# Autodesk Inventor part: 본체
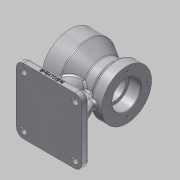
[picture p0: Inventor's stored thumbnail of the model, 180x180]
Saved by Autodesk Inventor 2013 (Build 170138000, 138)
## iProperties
Created: 2019-01
Part Number: 본체
Material: 알루미늄 6061
Document SubType Name: Modeling
Designer: dgall
Density: 2.71 g/cm^3
Mass: 902.149 g
Surface Area: 600.961 cm^2
Volume: 332.896 cm^3
Author: dgall
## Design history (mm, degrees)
sketch "스케치1"
  geometry: L1 (46, 46)-(-46, 46); L2 (-46, 46)-(-46, -46); L3 (-46, -46)-(46, -46); L4 (46, -46)-(46, 46); L5 (46, 46)-(-46, -46); L6 (-46, 46)-(46, -46); 1 further point
  constraints: 12 end point, 2 midpoint, 2 parallel, 1 horizontal, 1 perpendicular
  dimensions: "d0" = 92 distance of L1.end L2.end; "d2" = 92 distance of L2.end L3.end
extrude "돌출1" new body sketch "스케치1" distance "d3" = 10; taper "d4" = 0 deg
sketch "스케치2"
  geometry: L1 (46, -46)-(46, 46) reference; L2 (-46, 46)-(-46, -46) reference; L3 (-46, 0)-(-16, 0); L4 (-16, 0)-(36, 0); L5 (-0.801, -5)-(36, -5); L6 (36, -5)-(36, 5); L7 (36, 5)-(-0.801, 5); L8 (-5.291, -5)-(36, 5); L9 (36, -5)-(-5.291, 5); A1 r 16 centre (-16, 0) between (-0.801, 5) and (-0.801, -5); 2 further points
  constraints: 14 end point, 3 midpoint, 3 perpendicular, 2 parallel, 2 point on circle, 1 centre point, 1 coincident, 1 point on line
  dimensions: "d5" = 30 distance of L3.start L3.end; "d7" = 32 diameter of A1; "d8" = 10 distance from line of L1 L4.end; "d9" = 10 distance of L6.end L5.end
extrude "돌출2" join sketch "스케치2" distance "d10" = 70; taper "d11" = 0 deg
sketch "스케치3"
  geometry: L1 (36.801, 0)-(2.798, 72.92); L2 (46.801, -10)-(46.801, 0) reference; L3 (2.798, 72.92)-(46.801, 72.92); L4 (46.801, 72.92)-(36.801, 0); 1 further point
  constraints: 6 end point, 1 perpendicular
  dimensions: "d12" = 25 deg angle of L2 L1
extrude "돌출3" cut sketch "스케치3" distance "d13" = 70; taper "d14" = 0 deg
fillet "모깎기1" dims "d15" = 10
sketch "스케치4"
  geometry: L1 (0, 0)-(0, 80); L2 (-46, 10)-(-46, 0) reference; L3 (-51, 80)-(29, 80); L4 (-51, 80)-(-51, 120); L5 (-51, 120)-(-26, 120); L6 (-26, 120)-(-5.215, 108); L7 (-5.215, 108)-(8.126, 108); L8 (8.126, 108)-(14, 115); L9 (14, 115)-(29, 115); L10 (29, 80)-(29, 115)
  constraints: 18 end point, 4 perpendicular, 2 parallel, 1 vertical
  dimensions: "d16" = 80 distance of L1.start L1.end; "d19" = 80 distance of L3.start L3.end; "d20" = 5 distance from line of L2 L3.start; "d21" = 40 distance of L3.start L4.end; "d22" = 25 distance of L4.end L5.end; "d23" = 15 distance of L8.end L9.end; "d24" = 30 deg angle of L7 L6; "d25" = 50 deg angle of L7 L8; "d27" = 35 distance of L3.end L9.end; "d28" = 28 distance between parallel lines of L3 L7
revolve "회전1" sketch "스케치4" stored, may be unused: angle "d26" = 90 deg
sketch "스케치5"
  geometry: L1 (0, 0)-(0, 80); L2 (-51, 80)-(29, 80); L3 (-46, 10)-(-46, 0) reference; L4 (-51, 80)-(-51, 106); L5 (-51, 106)-(-31, 106); L6 (-31, 106)-(-31, 80); L7 (-31, 96)-(12, 96); L8 (12, 96)-(12, 80); L9 (12, 80)-(12, 100); L10 (12, 100)-(29, 100); L11 (29, 100)-(29, 80)
  constraints: 20 end point, 6 perpendicular, 3 point on line, 2 parallel, 1 collinear, 1 vertical
  dimensions: "d29" = 80 distance of L1.start L1.end; "d30" = 5 distance from line of L3 L2.start; "d31" = 80 distance of L2.start L2.end; "d32" = 20 distance of L4.end L5.end; "d33" = 26 distance of L2.start L4.end; "d34" = 16 distance of L7.end L8.end; "d35" = 17 distance of L9.end L10.end; "d36" = 20 distance of L10.end L2.end
revolve "회전2" sketch "스케치5" stored, may be unused: angle "d37" = 90 deg
sketch "스케치6"
  geometry: C1 r 4.5 at (36, 36); C2 r 4.5 at (36, -36); C3 r 4.5 at (-36, 36); C4 r 4.5 at (-36, -36); A1 r 10 centre (-36, 36) between (-36, 46) and (-46, 36) reference; A2 r 10 centre (-36, -36) between (-46, -36) and (-36, -46) reference; A3 r 10 centre (36, -36) between (36, -46) and (46, -36) reference; A4 r 10 centre (36, 36) between (46, 36) and (36, 46) reference; 1 further point
  constraints: 4 centre point, 4 coincident
  dimensions: "d38" = 9 diameter of C1; "d39" = 9 diameter of C2; "d40" = 9 diameter of C3; "d41" = 9 diameter of C4
extrude "돌출4" cut sketch "스케치6" distance "d42" = 70; taper "d43" = 0 deg
fillet "모깎기2" dims "d44" = 3
fillet "모깎기3" dims "d45" = 3
fillet "모깎기4" dims "d46" = 3
fillet "모깎기5" dims "d47" = 3
fillet "모깎기6" dims "d48" = 1
fillet "모깎기7" dims "d49" = 0.6
chamfer "모따기1" distance "d50" = 1; stored, may be unused: second distance "d51" = 2, angle "d52" = 45 deg
chamfer "모따기2" distance "d53" = 1; stored, may be unused: second distance "d54" = 2, angle "d55" = 45 deg
sketch "스케치7" dims "d56" = 66
  geometry: C1 r 27 at (0, 0) reference; 3 further points
  constraints: 1 coincident, 1 vertical alignment, 2 other
hole "구멍1" sketch "스케치7" at (0, 33) diameter "d58" = 3.242; stored, may be unused: countersink angle "d62" = 90 deg, drill point angle "d64" = 118 deg; dims "d59" = 9, "d60" = 4, "d61" = 2, "d63" = 11
sketch "스케치8" dims "d68" = 55
  geometry: C1 r 21 at (0, 0) reference; 3 further points
  constraints: 1 coincident, 1 vertical alignment, 2 other
hole "구멍2" sketch "스케치8" at (0, 27.5) diameter "d70" = 3.242; stored, may be unused: countersink angle "d74" = 90 deg, drill point angle "d76" = 118 deg; dims "d71" = 9, "d72" = 4, "d73" = 2, "d75" = 11
sketch "스케치9"
  geometry: L1 (0, 0)-(72, 0) reference; L2 (-10, 7)-(-10, 0) reference; 2 further points
  constraints: 1 other
  dimensions: "d80" = 4 distance from line of L1 point (36, 4); "d81" = 46 distance from line of L2 point (36, 4)
feature "엠보싱1" sketch "스케치9" dims "d0" = 92, "d2" = 92, "d82" = 0.5, "d83" = 0
node "솔리드1"
pattern_circular "원형 패턴1" dims angle "d66" = 360 deg
pattern_circular "원형 패턴2" dims angle "d78" = 360 deg
